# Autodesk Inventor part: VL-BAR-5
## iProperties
Created: 2005-08
Part Number: VL-BAR-5
Document SubType Name: Sheet Metal
Density: 1 g/cm^3
Mass: 0.845368 g
Surface Area: 16.5133 cm^2
Volume: 0.845368 cm^3
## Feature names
1. Rectangular Pattern1
2. Plate1
